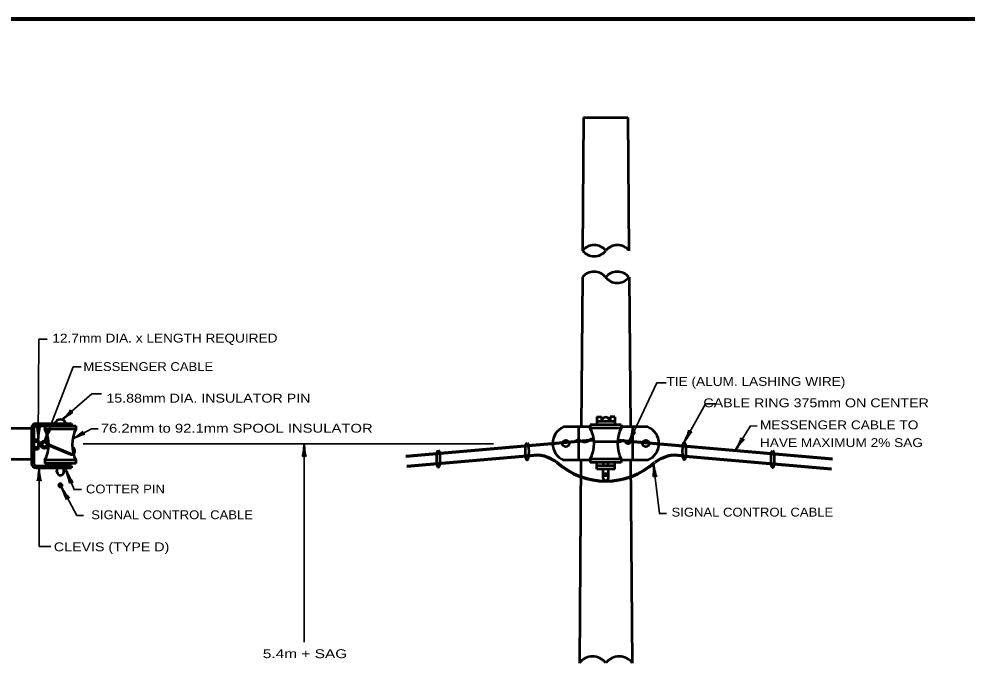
# Model space of a CAD drawing. Extents: x -421 to 434, y -46 to 498.
# Drawn here: x -181.8 to 74.7, y 317.6 to 491.9 of the extents above; entities that cross this region are included whole.
import ezdxf
from ezdxf.enums import TextEntityAlignment as Align

# ---------------------------------------------------------------- set-up
doc = ezdxf.new("R2010")
doc.units = 0
doc.header["$LTSCALE"] = 0.96
doc.layers.add('1', color=7, linetype='Continuous', lineweight=53)

msp = doc.modelspace()

# ---------------------------------------------------------------- hatches: boundary and pattern name
at = {"layer": '1'}
msp.add_hatch(color=256, dxfattribs=at).paths.add_polyline_path([(-169.9492, 365.6815, 1), (-171.1492, 365.6815, 1)])

# ---------------------------------------------------------------- linework, layer by layer
for p, q in [((-28.9996, 465.1862), (-29.2765, 429.1862)), ((-28.9996, 465.1862), (-16.9996, 465.1862)), ((-16.9996, 465.1862), (-16.7226, 429.1862)), ((-29.3319, 421.9862), (-29.6435, 381.4862)), ((-16.6673, 421.9862), (-16.3557, 381.4862)), ((-177.1464, 382.3862), (-167.5464, 382.3862)), ((-167.5464, 382.3862), (-167.5464, 381.7862)), ((-25.3996, 384.1862), (-25.3996, 382.0862)), ((-25.3996, 384.1862), (-24.1996, 384.1862)), ((-20.5996, 382.9862), (-25.3996, 382.9862)), ((-24.1996, 384.1862), (-24.1996, 382.9862)), ((-20.5996, 384.1862), (-21.7996, 384.1862)), ((-21.7996, 384.1862), (-21.7996, 382.9862)), ((-20.5996, 384.1862), (-20.5996, 382.0862)), ((-187.9464, 381.1862), (-178.3464, 381.1862)), ((-178.3464, 381.1862), (-178.3464, 371.5862)), ((-177.7464, 381.1862), (-177.7464, 371.5862)), ((-177.1464, 381.7862), (-166.3464, 381.7862)), ((-174.7464, 381.7862), (-174.7464, 380.8862)), ((-166.3464, 380.8862), (-174.7464, 380.8862)), ((-166.3464, 381.7862), (-166.3464, 380.8862)), ((-27.1996, 381.4862), (-34.3996, 381.4862)), ((-30.3128, 372.4862), (-30.3128, 381.4862)), ((-27.1996, 382.0862), (-27.1996, 381.1862)), ((-18.7996, 382.0862), (-27.1996, 382.0862)), ((-18.7996, 381.1862), (-27.1996, 381.1862)), ((-18.7996, 382.0862), (-18.7996, 381.1862)), ((-11.5996, 381.4862), (-18.7996, 381.4862)), ((-15.6866, 372.4862), (-15.6866, 381.4862)), ((-176.5464, 378.0362), (-177.7464, 378.0362)), ((-176.5464, 377.4362), (-177.7464, 377.4362)), ((-176.5464, 378.0362), (-176.5464, 375.3362)), ((-175.81, 377.1362), (-176.5464, 377.1362)), ((-19.8128, 377.4362), (-26.1864, 377.4362)), ((-176.5464, 375.9362), (-177.7464, 375.9362)), ((-176.5464, 375.3362), (-177.7464, 375.3362)), ((-175.7982, 376.2362), (-176.5464, 376.2362)), ((-187.9464, 372.7862), (-178.3464, 372.7862)), ((-166.3464, 372.4862), (-174.7464, 372.4862)), ((-174.7464, 372.4862), (-174.7464, 371.5862)), ((-166.3464, 372.4862), (-166.3464, 371.5862)), ((-27.1996, 372.4862), (-34.3996, 372.4862)), ((-29.7127, 372.4862), (-30.135, 317.5862)), ((-18.7996, 372.7862), (-27.1996, 372.7862)), ((-27.1996, 372.7862), (-27.1996, 371.8862)), ((-18.7996, 372.7862), (-18.7996, 371.8862)), ((-11.5996, 372.4862), (-18.7996, 372.4862)), ((-16.2865, 372.4862), (-15.8642, 317.5862)), ((-177.1464, 370.9862), (-167.5464, 370.9862)), ((-177.1464, 370.3862), (-167.5464, 370.3862)), ((-166.3464, 371.5862), (-174.7464, 371.5862)), ((-171.4464, 370.9862), (-171.4464, 371.5862)), ((-171.4464, 369.1862), (-171.4464, 370.3862)), ((-169.6464, 370.9862), (-169.6464, 371.5862)), ((-169.6464, 369.1862), (-169.6464, 370.3862)), ((-167.5464, 370.9862), (-167.5464, 370.3862)), ((-18.7996, 371.8862), (-27.1996, 371.8862)), ((-25.3996, 370.0862), (-25.3996, 371.8862)), ((-20.5996, 370.9862), (-25.3996, 370.9862)), ((-20.5996, 370.0862), (-25.3996, 370.0862)), ((-23.7496, 367.6862), (-23.7496, 370.0862)), ((-23.5996, 370.9862), (-23.5996, 371.8862)), ((-22.3996, 370.9862), (-22.3996, 371.8862)), ((-22.2496, 367.6862), (-22.2496, 370.0862)), ((-20.5996, 370.0862), (-20.5996, 371.8862))]:
    msp.add_line(p, q, dxfattribs=at)
at = {"layer": '1', "lineweight": 35}
for p, q in [((-176.5464, 378.0362), (-176.358, 405.2036)), ((-176.358, 405.2036), (-174.101, 405.2061)), ((-174.7353, 377.8468), (-167.1036, 397.7539)), ((-167.1036, 397.7539), (-164.9443, 397.7184)), ((-170.0527, 383.4782), (-162.0907, 390.4474)), ((-162.0907, 390.4474), (-159.4212, 390.4488)), ((-1.7973, 377.3344), (4.0133, 387.7057)), ((4.0133, 387.7057), (6.989, 387.7341)), ((12.2132, 375.3705), (16.1815, 381.7564)), ((16.1815, 381.7564), (17.9562, 381.7377)), ((-164.3862, 376.9296), (-53.3862, 376.9296)), ((-104.5875, 323.2579), (-104.5875, 376.9296)), ((-176.3137, 370.3207), (-176.3137, 349.1574)), ((-171.4464, 369.7862), (-171.8707, 370.2105)), ((-171.4464, 369.7862), (-171.8707, 369.3619)), ((-170.2106, 365.1104), (-166.1237, 357.4978)), ((-166.1237, 357.4978), (-164.2902, 357.5174)), ((-176.3137, 349.1574), (-173.1563, 349.1574))]:
    msp.add_line(p, q, dxfattribs=at)
at = {"layer": '1', "lineweight": 70}
for p, q in [((-26.2212, 377.8995), (-77.1071, 373.4476)), ((-19.7776, 377.9034), (38.3248, 372.82)), ((-173.7221, 376.6862), (-168.1079, 374.2898)), ((-43.3996, 373.6862), (-76.8717, 370.7578)), ((-2.5552, 373.6862), (38.0895, 370.1302)), ((-22.9996, 369.1862), (-22.9996, 367.9862))]:
    msp.add_line(p, q, dxfattribs=at)
at = {"layer": '1', "lineweight": 158}
msp.add_lwpolyline([(427.565, 491.8976), (-364.135, 491.7976), (-364.035, -34.2024)], dxfattribs=at)
at = {"layer": '1', "lineweight": 35}
for points in [[(-16.8786, 377.0666), (-9.2041, 393.4026), (-6.7054, 393.4026)], [(-167.2116, 378.2679), (-162.1082, 381.0046), (-160.3193, 381.0046)], [(-168.9479, 369.5839), (-166.8433, 364.5314), (-164.844, 364.5314)], [(-10.0965, 371.4427), (-8.4902, 358.0526), (-6.6162, 358.0526)]]:
    msp.add_lwpolyline(points, dxfattribs=at)
at = {"layer": '1'}
for centre, radius in [((-174.8555, 376.6986), 1.05), ((-174.848, 376.7306), 0.6266), ((-33.844, 376.9803), 0.9), ((-12.1686, 376.9803), 0.9)]:
    msp.add_circle(centre, radius, dxfattribs=at)
at = {"layer": '1', "lineweight": 35}
msp.add_circle((-170.5492, 365.6815), 0.6, dxfattribs=at)
at = {"layer": '1'}
for centre, radius, start, end in [((-26.138, 426.6838), 4.0159, 38.6004, 141.3996), ((-26.138, 431.6916), 4.0159, 218.6004, 321.3996), ((-19.8498, 426.6838), 4.0159, 38.6004, 141.3996), ((-26.1935, 419.4808), 4.0159, 38.6004, 141.3996), ((-19.9052, 419.4808), 4.0159, 38.6004, 141.3996), ((-19.9052, 424.4886), 4.0159, 218.6004, 321.3996), ((-177.1464, 381.1862), 1.2, 90, 180), ((-170.5464, 381.9764), 1.555, 15.28151, 164.71849), ((-22.9996, 383.0631), 1.0528, 355.80967, 184.19033), ((-177.1464, 381.1862), 0.6, 90, 180), ((-182.8454, 376.6862), 9.1232, 332.5894, 27.4106), ((-158.2474, 376.6862), 9.1232, 152.5894, 207.4106), ((-32.5032, 376.9862), 4.8833, 112.85129, 247.14871), ((-35.2986, 376.9862), 9.1232, 332.5894, 27.4106), ((-10.7006, 376.9862), 9.1232, 152.5894, 207.4106), ((-13.5094, 376.9862), 4.8833, 292.85129, 67.14871), ((-177.1464, 371.5862), 1.2, 180, 270), ((-177.1464, 371.5862), 0.6, 180, 270), ((-170.5464, 369.3), 0.9072, 187.20763, 352.79237), ((-22.9996, 367.733), 0.7515, 183.56726, 356.43274), ((-26.5673, 314.9498), 4.4479, 36.66818, 143.33182), ((-19.4081, 314.9498), 4.4479, 36.66818, 143.33182)]:
    msp.add_arc(centre, radius, start, end, dxfattribs=at)
at = {"layer": '1', "lineweight": 70}
for centre, radius, start, end in [((-167.5943, 374.9876), 0.8665, 233.64544, 71.83182), ((-41.8786, 364.4702), 9.3406, 52.55588, 99.37163), ((-4.0762, 364.4702), 9.3406, 80.62837, 127.44412), ((-22.9996, 386.5614), 19.7383, 228.02939, 311.9706)]:
    msp.add_arc(centre, radius, start, end, dxfattribs=at)
at = {"layer": '1', "lineweight": 35}
for centre, radius, start, end in [((-169.1558, 369.5634), 0.5604, 108.38064, 151.10471), ((-169.1585, 370.0047), 0.5565, 208.73791, 251.77673), ((-169.2507, 369.7857), 0.3201, 255.19279, 104.80721)]:
    msp.add_arc(centre, radius, start, end, dxfattribs=at)
at = {"layer": '1', "lineweight": 40}
for centre, major_axis, ratio, start_param, end_param in [((-169.2858, 384.5901), (-1.489, -1.5523), 0.122415, 0.89635335, 3.14159265), ((-169.2858, 384.5901), (-1.489, -1.5523), 0.122415, 0.89635335, 3.14159265), ((-168.8737, 384.1727), (-1.7248, -1.2296), 0.07063, 3.14071475, 5.41810995), ((-168.8737, 384.1727), (-1.7248, -1.2296), 0.07063, 3.14071475, 5.41810995), ((-176.8689, 379.3479), (0.1725, -2.1441), 0.122415, 0.89635335, 3.14159265), ((-176.8689, 379.3479), (0.1725, -2.1441), 0.122415, 0.89635335, 3.14159265), ((-176.2832, 379.379), (0.2254, 2.1062), 0.07063, 6.28230741, 8.55970261), ((-176.2832, 379.379), (0.2254, 2.1062), 0.07063, 6.28230741, 8.55970261), ((-174.5762, 379.1882), (-0.5921, -2.0679), 0.122415, 0.89635335, 3.14159265), ((-174.5762, 379.1882), (-0.5921, -2.0679), 0.122415, 0.89635335, 3.14159265), ((-174.0169, 379.0114), (0.9513, 1.8926), 0.07063, 6.28230741, 8.55970261), ((-174.0169, 379.0114), (0.9513, 1.8926), 0.07063, 6.28230741, 8.55970261), ((-166.2143, 379.1789), (-1.7999, -1.1778), 0.122415, 0.89635335, 3.14159265), ((-166.2143, 379.1789), (-1.7999, -1.1778), 0.122415, 0.89635335, 3.14159265), ((-16.6219, 378.3928), (-0.7416, -2.0192), 0.122415, 0.89635335, 3.14159265), ((-16.6219, 378.3928), (-0.7416, -2.0192), 0.122415, 0.89635335, 3.14159265), ((-16.077, 378.1756), (-1.087, -1.8181), 0.07063, 3.14071475, 5.41810995), ((-16.077, 378.1756), (-1.087, -1.8181), 0.07063, 3.14071475, 5.41810995), ((-1.4465, 378.6388), (-0.8839, -1.961), 0.122415, 0.89635335, 3.14159265), ((-1.4465, 378.6388), (-0.8839, -1.961), 0.122415, 0.89635335, 3.14159265), ((-0.9186, 378.3833), (1.2141, 1.7358), 0.07063, 6.28230741, 8.55970261), ((-0.9186, 378.3833), (1.2141, 1.7358), 0.07063, 6.28230741, 8.55970261), ((-165.9066, 378.6796), (1.9571, 0.8103), 0.07063, 6.28230741, 8.55970261), ((-165.9066, 378.6796), (1.9571, 0.8103), 0.07063, 6.28230741, 8.55970261), ((12.6227, 376.6577), (-0.9719, -1.919), 0.122415, 0.89635335, 3.14159265), ((12.6227, 376.6577), (-0.9719, -1.919), 0.122415, 0.89635335, 3.14159265), ((13.1386, 376.3785), (1.2915, 1.679), 0.07063, 6.28230741, 8.55970261), ((13.1386, 376.3785), (1.2915, 1.679), 0.07063, 6.28230741, 8.55970261), ((-104.8414, 375.585), (0.2108, 2.1077), 0.07063, 3.14071475, 5.41810995), ((-104.8414, 375.585), (0.2108, 2.1077), 0.07063, 3.14071475, 5.41810995), ((-104.2559, 375.6202), (-0.1874, 2.1428), 0.122415, 0.89635335, 3.14159265), ((-104.2559, 375.6202), (-0.1874, 2.1428), 0.122415, 0.89635335, 3.14159265), ((-176.5676, 368.9761), (0.2108, 2.1077), 0.07063, 3.14071475, 5.41810995), ((-175.9821, 369.0113), (-0.1874, 2.1428), 0.122415, 0.89635335, 3.14159265), ((-168.6653, 368.245), (-0.6159, 2.0267), 0.07063, 3.14071475, 5.41810995), ((-168.6653, 368.245), (-0.6159, 2.0267), 0.07063, 3.14071475, 5.41810995), ((-168.1383, 368.5026), (-0.9969, 1.906), 0.122415, 0.89635335, 3.14159265), ((-168.1383, 368.5026), (-0.9969, 1.906), 0.122415, 0.89635335, 3.14159265), ((-10.1885, 370.0774), (-0.0418, 2.1178), 0.07063, 3.14071475, 5.41810995), ((-9.6113, 370.1821), (-0.4413, 2.1053), 0.122415, 0.89635335, 3.14159265), ((-169.7983, 363.8056), (0.8113, -1.9567), 0.07063, 6.28230741, 8.55970261), ((-169.7983, 363.8056), (0.8113, -1.9567), 0.07063, 6.28230741, 8.55970261), ((-169.2991, 364.1135), (-1.1787, 1.7993), 0.122415, 0.89635335, 3.14159265), ((-169.2991, 364.1135), (-1.1787, 1.7993), 0.122415, 0.89635335, 3.14159265)]:
    msp.add_ellipse(centre, major_axis=major_axis, ratio=ratio, start_param=start_param, end_param=end_param, dxfattribs=at)
at = {"layer": '1'}
for centre in [(-44.2835, 374.8569), (-1.7788, 374.9367), (-68.3142, 372.8586), (22.1451, 372.7828)]:
    msp.add_ellipse(centre, major_axis=(0, 2.3609), ratio=0.186637, dxfattribs=at)
for points in [[(-26.1864, 377.4362), (-26.4781, 378.0282), (-26.9722, 378.1576), (-27.3017, 378.0046), (-27.5252, 377.8869), (-27.6664, 377.6868), (-27.7841, 377.628), (-28.09, 377.4868), (-28.6783, 377.3573), (-29.1372, 377.3691), (-29.7255, 377.6751), (-30.1491, 377.8516), (-30.5844, 377.8987), (-30.8433, 377.8516), (-31.0551, 377.7575), (-31.2551, 377.6162), (-31.4198, 377.4515)], [(-19.8128, 377.4362), (-19.5331, 377.3867), (-19.0362, 377.506), (-18.738, 377.685), (-18.4995, 377.844), (-18.3008, 377.9037), (-17.9231, 377.7049), (-17.7641, 377.506), (-17.5455, 377.2873), (-17.466, 377.2078), (-17.2473, 377.0686), (-16.8299, 377.0289), (-16.5318, 377.168), (-16.2138, 377.4265), (-16.0548, 377.6253)]]:
    msp.add_spline(points, degree=3, dxfattribs=at)

# ---------------------------------------------------------------- texts
for s, width, p in [('12.7mm DIA. x LENGTH REQUIRED', 1.15, (-142.2704, 404.3294)), ('MESSENGER CABLE', 1.1, (-146.7779, 396.6115)), ('TIE (ALUM. LASHING WIRE)', 1.15, (17.6156, 392.5986)), ('15.88mm DIA. INSULATOR PIN', 1.2, (-130.5174, 388.0645)), ('CABLE RING 375mm ON CENTER', 1.2, (33.9055, 386.8066)), ('76.2mm to 92.1mm SPOOL INSULATOR', 1.25, (-122.8523, 379.9313)), ('COTTER PIN', 1.1, (-152.9648, 363.4895)), ('SIGNAL CONTROL CABLE', 1.1, (16.662, 357.2334)), ('SIGNAL CONTROL CABLE', 1.1, (-140.3347, 356.5157)), ('CLEVIS (TYPE D)', 1.2, (-156.7081, 347.8316)), ('5.4m + SAG', 1.3, (-104.3684, 318.9169))]:
    msp.add_text(s, height=2.4, dxfattribs=dict(at, width=width)).set_placement(p, align=Align.CENTER)
at = {"layer": '1', "width": 1.15}
for s, p in [('MESSENGER CABLE TO', (18.7055, 380.8368)), ('HAVE MAXIMUM 2% SAG', (18.7055, 376.0368))]:
    msp.add_text(s, height=2.4, dxfattribs=at).set_placement(p)

doc.saveas('drawing.dxf')
